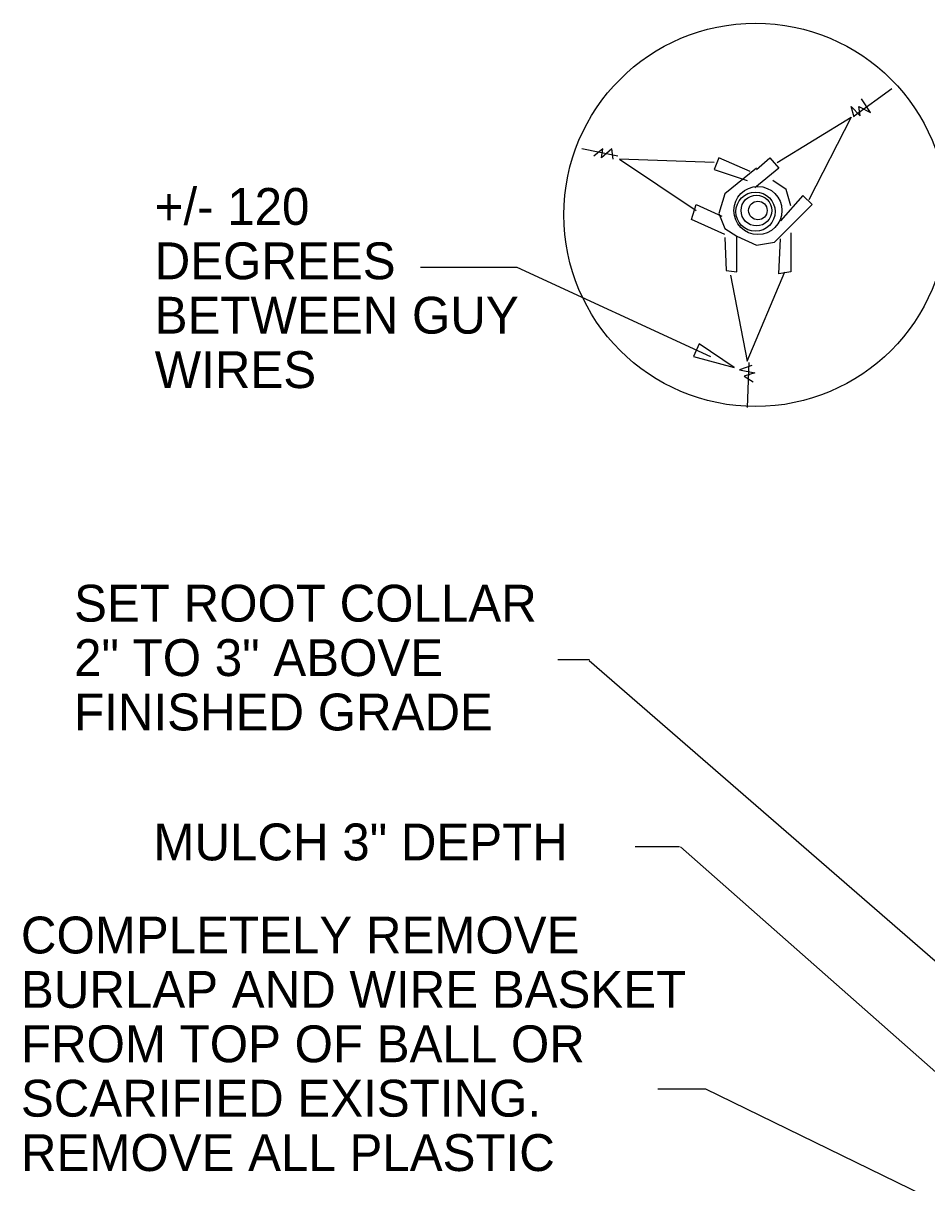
# Model space of a CAD drawing. Extents: x 10082 to 10257, y 10014 to 10069.
# Drawn here: x 10113.28 to 10130.45, y 10029.99 to 10052.02 of the extents above; entities that cross this region are included whole.
import ezdxf

# ---------------------------------------------------------------- set-up
doc = ezdxf.new("R2010")
doc.units = 0
for name, color, linetype in [('Default', 7, 'Continuous'), ('G-DETL-LINE', 7, 'Continuous'), ('G-DETL-TEXT', 7, 'Continuous')]:
    doc.layers.add(name, color=color, linetype=linetype)

msp = doc.modelspace()

# ---------------------------------------------------------------- linework, layer by layer
at = {"layer": 'Default'}
for p, q in [((10122.666, 10047.376), (10120.827, 10047.376)), ((10126.346, 10045.684), (10122.666, 10047.376)), ((10124.038, 10039.928), (10123.436, 10039.928)), ((10136.436, 10029.143), (10124.034, 10039.908)), ((10125.752, 10036.373), (10124.907, 10036.373)), ((10134.238, 10028.901), (10125.771, 10036.373)), ((10126.252, 10031.772), (10125.337, 10031.772)), ((10134.989, 10027.512), (10126.252, 10031.772))]:
    msp.add_line(p, q, dxfattribs=at)
msp.add_lwpolyline([(10126.126, 10045.929), (10126.016, 10045.691), (10126.785, 10045.482)], close=True, dxfattribs=at)
at = {"layer": 'G-DETL-LINE'}
for points in [[(10129.066, 10050.262), (10129.781, 10050.78)], [(10129.066, 10050.234), (10129.011, 10050.438), (10129.181, 10050.262), (10129.154, 10050.438), (10129.38, 10050.322), (10129.209, 10050.581)], [(10127.607, 10049.375), (10129.011, 10050.234), (10128.207, 10048.665)], [(10124.58, 10049.491), (10123.892, 10049.634)], [(10124.492, 10049.436), (10124.465, 10049.634), (10124.266, 10049.463), (10124.294, 10049.634), (10124.123, 10049.491)], [(10127.095, 10049.204), (10126.495, 10049.463), (10126.407, 10049.237), (10127.035, 10049.034)], [(10127.211, 10049.237), (10127.464, 10049.463), (10127.635, 10049.265), (10127.178, 10048.89)], [(10126.407, 10049.375), (10124.608, 10049.436), (10126.066, 10048.461)], [(10127.211, 10049.265), (10126.611, 10048.775), (10126.495, 10048.406), (10126.611, 10048.119), (10126.837, 10047.976), (10127.211, 10047.805), (10127.552, 10047.86), (10128.268, 10048.576), (10128.092, 10048.747), (10127.668, 10048.263)], [(10127.866, 10048.549), (10127.778, 10048.863), (10127.525, 10049.034)], [(10126.611, 10048.004), (10125.978, 10048.29), (10126.066, 10048.576), (10126.551, 10048.351)], [(10126.611, 10047.949), (10126.639, 10047.321), (10126.837, 10047.293), (10126.837, 10047.976)], [(10127.866, 10048.037), (10127.866, 10047.293), (10127.635, 10047.26), (10127.668, 10047.921)], [(10126.721, 10047.233), (10127.035, 10045.602), (10127.75, 10047.293)], [(10127.123, 10045.52), (10126.892, 10045.432), (10127.178, 10045.377), (10126.98, 10045.316), (10127.15, 10045.206)], [(10127.068, 10045.575), (10127.035, 10044.716)]]:
    msp.add_lwpolyline(points, dxfattribs=at)
for centre, radius in [((10127.194, 10048.378), 3.641), ((10127.239, 10048.461), 0.457), ((10127.194, 10048.439), 0.373), ((10127.211, 10048.461), 0.292), ((10127.239, 10048.461), 0.176)]:
    msp.add_circle(centre, radius, dxfattribs=at)

# ---------------------------------------------------------------- texts
at = {"layer": 'G-DETL-TEXT'}
for s, p in [('+/- 120 ', (10115.778, 10048.188)), ('DEGREES ', (10115.778, 10047.155)), ('BETWEEN GUY ', (10115.778, 10046.122)), ('WIRES', (10115.778, 10045.088)), ('SET ROOT COLLAR ', (10114.247, 10040.652)), ('2" TO 3" ABOVE ', (10114.247, 10039.618)), ('FINISHED GRADE', (10114.247, 10038.585)), ('MULCH 3" DEPTH', (10115.754, 10036.117)), ('COMPLETELY REMOVE ', (10113.237, 10034.349)), ('BURLAP AND WIRE BASKET ', (10113.237, 10033.316)), ('FROM TOP OF BALL OR ', (10113.237, 10032.282)), ('SCARIFIED EXISTING. ', (10113.237, 10031.249)), ('REMOVE ALL PLASTIC ', (10113.237, 10030.216))]:
    msp.add_text(s, height=0.7, dxfattribs=at).set_placement(p)

doc.saveas('drawing.dxf')
